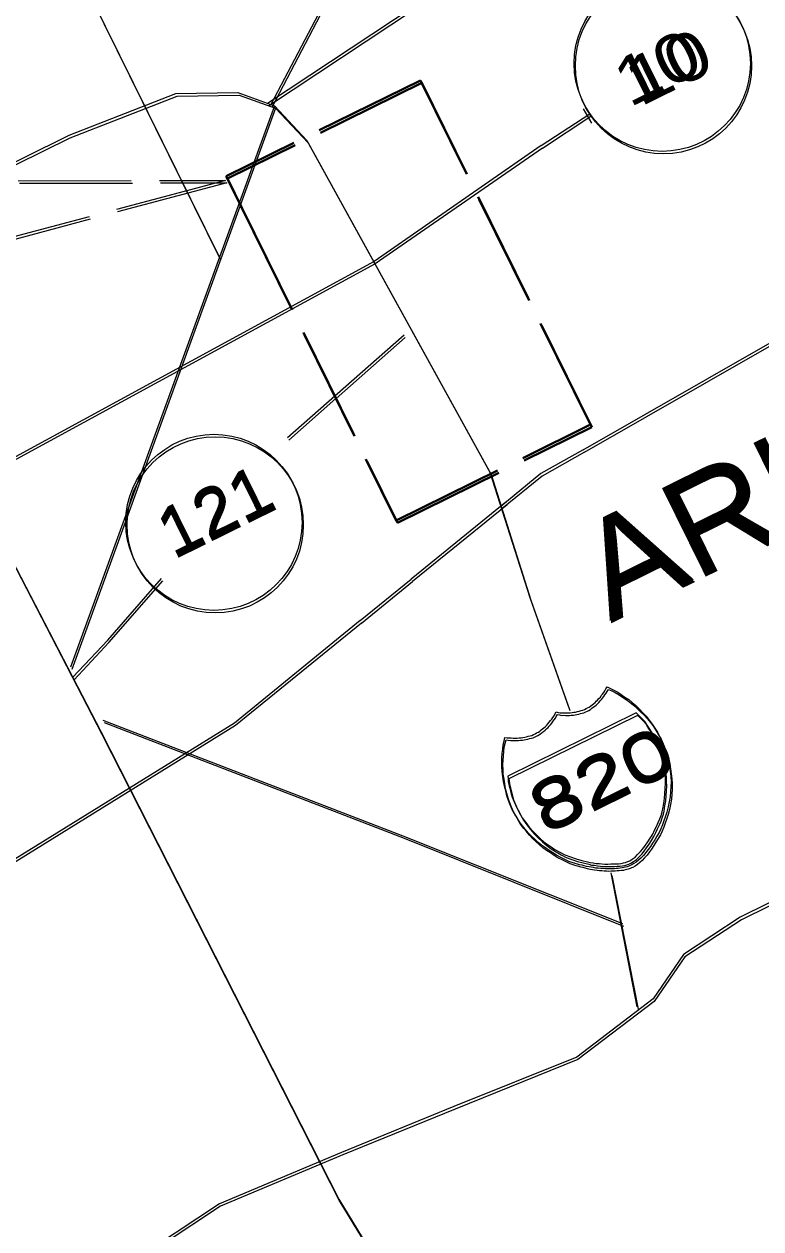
# Model space of a CAD drawing. Extents: x 2356606 to 2371222, y 6973096 to 6982644.
# Drawn here: x 2357285.3 to 2357363.6, y 6973619.6 to 6973747.7 of the extents above; entities that cross this region are included whole.
import ezdxf

# ---------------------------------------------------------------- set-up
doc = ezdxf.new("R2010")
doc.units = 0
doc.header["$LTSCALE"] = 2
doc.linetypes.add('LONG_DASHED', pattern=[7.5, 6, -1.5])
doc.layers.add('62', color=7, linetype='Continuous', lineweight=13)
doc.layers.add('63', color=7, linetype='Continuous', lineweight=13)

msp = doc.modelspace()

# ---------------------------------------------------------------- linework, layer by layer
at = {"layer": '62'}
for p, q in [((2357306.189, 6973722.639), (2357286.779, 6973761.966)), ((2357312.029, 6973738.72), (2357290.372, 6973679.028)), ((2357340.392, 6973734.479), (2357345.545, 6973737.873)), ((2357344.863, 6973738.391), (2357345.59, 6973737.12)), ((2357318.452, 6973707.86), (2357325.81, 6973714.355)), ((2357313.435, 6973703.432), (2357318.451, 6973707.861)), ((2357294.325, 6973681.906), (2357300.042, 6973688.465)), ((2357294.325, 6973681.906), (2357290.63, 6973677.95))]:
    msp.add_line(p, q, dxfattribs=at)
at = {"layer": '62', "lineweight": 25}
for p, q in [((2357312.029, 6973738.72), (2357315.48, 6973735.03)), ((2357315.48, 6973735.03), (2357334.942, 6973699.767)), ((2357344.853, 6973702.151), (2357364.72, 6973713.512)), ((2357336.626, 6973696.558), (2357326.581, 6973688.388)), ((2357321.156, 6973683.979), (2357326.581, 6973688.388)), ((2357347.774, 6973657.142), (2357350.558, 6973642.91))]:
    msp.add_line(p, q, dxfattribs=at)
at = {"layer": '62'}
for points in [[(2357324.805, 6973765.304), (2357320.284, 6973755.34), (2357311.656, 6973738.864)], [(2357311.295, 6973738.987), (2357326.895, 6973749.32), (2357341.679, 6973758.824)], [(2357340.392, 6973734.479), (2357322.629, 6973722.171), (2357280.124, 6973699.034), (2357274.052, 6973694.657)], [(2357342.838, 6973674.156), (2357343.061, 6973674.166), (2357343.263, 6973674.163), (2357343.454, 6973674.183), (2357343.675, 6973674.192), (2357343.856, 6973674.231), (2357344.048, 6973674.249), (2357344.25, 6973674.3), (2357344.42, 6973674.359), (2357344.621, 6973674.408), (2357344.802, 6973674.447), (2357344.985, 6973674.538), (2357345.166, 6973674.627), (2357345.308, 6973674.697), (2357345.489, 6973674.786), (2357345.65, 6973674.916), (2357345.792, 6973675.036), (2357345.946, 6973675.135), (2357346.104, 6973675.266), (2357346.238, 6973675.407), (2357346.377, 6973675.526), (2357346.52, 6973675.697), (2357346.671, 6973675.847), (2357346.773, 6973675.998), (2357346.915, 6973676.168), (2357347.026, 6973676.348), (2357347.147, 6973676.51), (2357347.268, 6973676.717), (2357347.391, 6973676.929), (2357347.754, 6973676.758), (2357348.115, 6973676.582), (2357348.526, 6973676.359), (2357348.896, 6973676.117), (2357349.279, 6973675.852), (2357349.69, 6973675.579), (2357350.07, 6973675.264), (2357350.431, 6973674.941), (2357350.82, 6973674.558), (2357351.182, 6973674.183), (2357351.541, 6973673.808), (2357351.872, 6973673.395), (2357352.181, 6973672.971), (2357352.47, 6973672.535), (2357352.731, 6973672.111), (2357352.991, 6973671.637), (2357353.208, 6973671.144), (2357353.426, 6973670.598), (2357353.616, 6973670.064), (2357353.785, 6973669.572), (2357353.923, 6973669.036), (2357354, 6973668.473), (2357354.079, 6973667.961), (2357354.145, 6973667.414), (2357354.183, 6973666.883), (2357354.161, 6973666.317), (2357354.137, 6973665.804), (2357354.086, 6973665.249), (2357353.981, 6973664.697), (2357353.887, 6973664.173), (2357353.733, 6973663.622), (2357353.573, 6973663.089), (2357353.416, 6973662.687), (2357353.274, 6973662.265), (2357353.101, 6973661.854), (2357352.917, 6973661.462), (2357352.682, 6973661.069), (2357352.45, 6973660.681), (2357352.228, 6973660.319), (2357351.984, 6973659.949), (2357351.761, 6973659.638), (2357351.518, 6973659.317), (2357351.245, 6973659.006), (2357350.982, 6973658.726), (2357350.748, 6973658.537), (2357350.487, 6973658.305), (2357350.245, 6973658.136), (2357350.011, 6973657.996)], [(2357350.011, 6973657.996), (2357349.841, 6973657.937), (2357349.7, 6973657.867), (2357349.507, 6973657.797), (2357349.348, 6973657.767), (2357349.166, 6973657.729), (2357348.985, 6973657.688), (2357348.773, 6973657.661), (2357348.559, 6973657.63), (2357348.342, 6973657.622), (2357348.129, 6973657.593), (2357347.876, 6973657.594), (2357347.677, 6973657.595), (2357347.434, 6973657.577), (2357347.202, 6973657.586), (2357346.941, 6973657.609), (2357346.71, 6973657.621), (2357346.447, 6973657.642), (2357346.187, 6973657.664), (2357345.937, 6973657.715), (2357345.713, 6973657.757), (2357345.472, 6973657.788), (2357345.192, 6973657.85), (2357344.939, 6973657.901), (2357344.729, 6973657.974), (2357344.457, 6973658.015), (2357344.246, 6973658.086), (2357343.985, 6973658.158), (2357343.774, 6973658.228), (2357343.532, 6973658.311), (2357343.323, 6973658.382), (2357343.121, 6973658.485), (2357342.899, 6973658.576), (2357342.468, 6973658.787), (2357342.026, 6973659.023), (2357341.623, 6973659.278), (2357341.244, 6973659.541), (2357340.833, 6973659.813), (2357340.42, 6973660.089), (2357340.069, 6973660.393), (2357339.701, 6973660.738), (2357339.35, 6973661.042), (2357339.01, 6973661.427), (2357338.699, 6973661.8), (2357338.39, 6973662.174), (2357338.088, 6973662.578), (2357337.83, 6973663.001), (2357337.551, 6973663.466), (2357337.31, 6973663.9), (2357337.092, 6973664.393), (2357336.913, 6973664.858), (2357336.746, 6973665.351), (2357336.616, 6973665.866), (2357336.47, 6973666.37), (2357336.392, 6973666.882), (2357336.312, 6973667.396), (2357336.226, 6973667.931), (2357336.209, 6973668.423), (2357336.19, 6973668.917), (2357336.201, 6973669.397), (2357336.245, 6973669.873), (2357336.298, 6973670.326), (2357336.33, 6973670.768), (2357336.434, 6973671.17), (2357336.517, 6973671.563), (2357336.758, 6973671.531), (2357336.999, 6973671.499), (2357337.201, 6973671.497), (2357337.411, 6973671.479), (2357337.632, 6973671.486), (2357337.833, 6973671.485), (2357338.046, 6973671.515), (2357338.267, 6973671.523), (2357338.429, 6973671.553), (2357338.64, 6973671.582), (2357338.821, 6973671.621), (2357339.01, 6973671.689), (2357339.213, 6973671.739), (2357339.396, 6973671.777), (2357339.556, 6973671.858), (2357339.74, 6973671.947), (2357339.9, 6973672.028), (2357340.082, 6973672.118), (2357340.225, 6973672.239), (2357340.385, 6973672.366), (2357340.516, 6973672.457), (2357340.678, 6973672.586), (2357340.829, 6973672.736), (2357340.992, 6973672.868), (2357341.092, 6973673.018), (2357341.244, 6973673.17), (2357341.386, 6973673.339), (2357341.507, 6973673.499), (2357341.622, 6973673.679), (2357341.76, 6973673.85), (2357341.845, 6973674.04), (2357341.984, 6973674.261), (2357342.185, 6973674.21), (2357342.406, 6973674.168), (2357342.627, 6973674.177), (2357342.838, 6973674.156)], [(2357349.044, 6973651.722), (2357325.734, 6973661.072), (2357293.846, 6973673.362)]]:
    msp.add_lwpolyline(points, dxfattribs=at)
at = {"layer": '62', "linetype": 'LONG_DASHED', "lineweight": 40}
msp.add_lwpolyline([(2357308.481, 6973728.063), (2357324.982, 6973694.628), (2357345.626, 6973704.814), (2357327.561, 6973741.417), (2357306.917, 6973731.231)], close=True, dxfattribs=at)
at = {"layer": '62', "lineweight": 25}
for points in [[(2357222.847, 6973670.893), (2357228.918, 6973681.166), (2357239.427, 6973691.649), (2357246.285, 6973700.327), (2357253.234, 6973708.874), (2357262, 6973718.52), (2357266.949, 6973724.101), (2357275.91, 6973728.522), (2357290.215, 6973735.582), (2357301.579, 6973740.013), (2357308.151, 6973740.118), (2357312.029, 6973738.72)], [(2357271.1, 6973715.534), (2357293.579, 6973672.174), (2357318.873, 6973622.455), (2357356.041, 6973561.379), (2357384.703, 6973540.469)], [(2357344.853, 6973702.151), (2357340.364, 6973699.609), (2357336.089, 6973696.118)], [(2357334.942, 6973699.767), (2357339.169, 6973686.421), (2357343.306, 6973674.686)], [(2357321.156, 6973683.979), (2357307.783, 6973673.088), (2357282.978, 6973657.708), (2357265.622, 6973642.845), (2357259.668, 6973639.454)], [(2357397.532, 6973674.071), (2357391.187, 6973669.235), (2357382.618, 6973664.025), (2357370.494, 6973656.862), (2357361.535, 6973652.442), (2357355.506, 6973648.488), (2357352.272, 6973643.756), (2357344.159, 6973637.568), (2357331.099, 6973632.303), (2357319.179, 6973627.424), (2357306.189, 6973621.966), (2357287.579, 6973609.643), (2357267.547, 6973602.895), (2357250.669, 6973598.906), (2357239.274, 6973599.379), (2357230.661, 6973609.861), (2357224.807, 6973621.723), (2357220.224, 6973626.738), (2357220.552, 6973637.313)]]:
    msp.add_lwpolyline(points, dxfattribs=at)
at = {"layer": '62', "linetype": 'LONG_DASHED'}
for points in [[(2357239.812, 6973730.633), (2357306.835, 6973730.788), (2357247.289, 6973714.873)], [(2357239.812, 6973730.633), (2357306.835, 6973730.788), (2357247.289, 6973714.873), (2357239.812, 6973730.633)]]:
    msp.add_lwpolyline(points, close=True, dxfattribs=at)
at = {"layer": '62'}
msp.add_lwpolyline([(2357350.487, 6973674.166), (2357336.827, 6973667.424), (2357336.863, 6973667.193), (2357336.892, 6973666.88), (2357336.953, 6973666.559), (2357337.071, 6973666.165), (2357337.17, 6973665.712), (2357337.297, 6973665.197), (2357337.515, 6973664.704), (2357337.775, 6973664.13), (2357338.064, 6973663.592), (2357338.372, 6973663.019), (2357338.743, 6973662.525), (2357339.112, 6973662.029), (2357339.523, 6973661.555), (2357339.924, 6973661.149), (2357340.393, 6973660.705), (2357340.856, 6973660.331), (2357341.329, 6973659.983), (2357341.837, 6973659.658), (2357342.374, 6973659.343), (2357342.915, 6973659.06), (2357343.496, 6973658.845), (2357344.098, 6973658.642), (2357344.7, 6973658.486), (2357345.324, 6973658.341), (2357345.595, 6973658.249), (2357345.908, 6973658.229), (2357346.24, 6973658.166), (2357346.551, 6973658.145), (2357346.842, 6973658.111), (2357347.154, 6973658.091), (2357347.455, 6973658.089), (2357347.779, 6973658.099), (2357348.051, 6973658.108), (2357348.321, 6973658.115), (2357348.614, 6973658.133), (2357348.876, 6973658.163), (2357349.128, 6973658.211), (2357349.349, 6973658.271), (2357349.579, 6973658.36), (2357349.794, 6973658.44), (2357350.056, 6973658.618), (2357350.378, 6973658.829), (2357350.621, 6973659.1), (2357350.945, 6973659.41), (2357351.199, 6973659.71), (2357351.462, 6973660.09), (2357351.726, 6973660.472), (2357351.968, 6973660.844), (2357352.234, 6973661.274), (2357352.426, 6973661.697), (2357352.63, 6973662.098), (2357352.824, 6973662.519), (2357353.005, 6973662.909), (2357353.128, 6973663.271), (2357353.24, 6973663.654), (2357353.314, 6973663.965), (2357353.406, 6973664.539), (2357353.489, 6973665.083), (2357353.532, 6973665.606), (2357353.566, 6973666.149), (2357353.598, 6973666.644), (2357353.58, 6973667.137), (2357353.571, 6973667.61), (2357353.514, 6973668.084), (2357353.456, 6973668.557), (2357353.378, 6973668.969), (2357353.28, 6973669.421), (2357353.132, 6973669.825), (2357353.001, 6973670.239), (2357352.854, 6973670.642), (2357352.684, 6973671.034), (2357352.525, 6973671.407), (2357352.225, 6973671.964), (2357351.947, 6973672.429), (2357351.638, 6973672.853), (2357351.397, 6973673.236), (2357351.119, 6973673.551), (2357350.878, 6973673.782), (2357350.668, 6973674.004)], close=True, dxfattribs=at)
for centre in [(2357353.248, 6973743.227), (2357305.613, 6973694.422)]:
    msp.add_circle(centre, 9.364, dxfattribs=at)
at = {"layer": '63'}
for p, q in [((2357306.059, 6973722.902), (2357286.649, 6973762.229)), ((2357311.899, 6973738.983), (2357290.242, 6973679.291)), ((2357340.262, 6973734.742), (2357345.415, 6973738.136)), ((2357344.733, 6973738.654), (2357345.46, 6973737.383)), ((2357318.321, 6973708.124), (2357325.679, 6973714.619)), ((2357313.305, 6973703.695), (2357318.321, 6973708.124)), ((2357294.195, 6973682.169), (2357299.912, 6973688.728)), ((2357294.195, 6973682.169), (2357290.5, 6973678.213))]:
    msp.add_line(p, q, dxfattribs=at)
at = {"layer": '63', "lineweight": 25}
for p, q in [((2357311.899, 6973738.983), (2357315.35, 6973735.293)), ((2357315.349, 6973735.294), (2357334.811, 6973700.031)), ((2357344.723, 6973702.414), (2357364.59, 6973713.775)), ((2357336.496, 6973696.821), (2357326.451, 6973688.651)), ((2357321.026, 6973684.242), (2357326.451, 6973688.651)), ((2357347.644, 6973657.405), (2357350.428, 6973643.173))]:
    msp.add_line(p, q, dxfattribs=at)
at = {"layer": '63'}
for points in [[(2357324.675, 6973765.567), (2357320.154, 6973755.603), (2357311.526, 6973739.127)], [(2357311.165, 6973739.25), (2357326.765, 6973749.583), (2357341.549, 6973759.087)], [(2357340.262, 6973734.742), (2357322.499, 6973722.434), (2357279.994, 6973699.297), (2357273.922, 6973694.92)], [(2357342.708, 6973674.419), (2357342.931, 6973674.429), (2357343.133, 6973674.426), (2357343.324, 6973674.446), (2357343.545, 6973674.455), (2357343.726, 6973674.494), (2357343.918, 6973674.512), (2357344.12, 6973674.563), (2357344.29, 6973674.622), (2357344.491, 6973674.671), (2357344.672, 6973674.71), (2357344.855, 6973674.801), (2357345.036, 6973674.89), (2357345.178, 6973674.96), (2357345.359, 6973675.049), (2357345.52, 6973675.179), (2357345.662, 6973675.299), (2357345.816, 6973675.398), (2357345.974, 6973675.529), (2357346.108, 6973675.67), (2357346.247, 6973675.789), (2357346.39, 6973675.96), (2357346.541, 6973676.11), (2357346.643, 6973676.261), (2357346.785, 6973676.431), (2357346.896, 6973676.611), (2357347.017, 6973676.773), (2357347.138, 6973676.98), (2357347.261, 6973677.192), (2357347.624, 6973677.021), (2357347.985, 6973676.845), (2357348.396, 6973676.622), (2357348.766, 6973676.38), (2357349.149, 6973676.115), (2357349.56, 6973675.842), (2357349.94, 6973675.527), (2357350.301, 6973675.204), (2357350.69, 6973674.821), (2357351.052, 6973674.446), (2357351.411, 6973674.071), (2357351.742, 6973673.658), (2357352.051, 6973673.234), (2357352.34, 6973672.798), (2357352.601, 6973672.374), (2357352.861, 6973671.9), (2357353.078, 6973671.407), (2357353.296, 6973670.861), (2357353.486, 6973670.327), (2357353.655, 6973669.835), (2357353.793, 6973669.299), (2357353.87, 6973668.736), (2357353.949, 6973668.224), (2357354.015, 6973667.677), (2357354.053, 6973667.146), (2357354.031, 6973666.58), (2357354.007, 6973666.067), (2357353.956, 6973665.512), (2357353.851, 6973664.96), (2357353.757, 6973664.436), (2357353.603, 6973663.885), (2357353.443, 6973663.352), (2357353.286, 6973662.95), (2357353.144, 6973662.528), (2357352.971, 6973662.117), (2357352.787, 6973661.725), (2357352.552, 6973661.332), (2357352.32, 6973660.944), (2357352.098, 6973660.582), (2357351.854, 6973660.212), (2357351.631, 6973659.901), (2357351.388, 6973659.58), (2357351.115, 6973659.269), (2357350.852, 6973658.989), (2357350.618, 6973658.8), (2357350.357, 6973658.568), (2357350.115, 6973658.399), (2357349.881, 6973658.259)], [(2357349.881, 6973658.259), (2357349.711, 6973658.2), (2357349.57, 6973658.13), (2357349.377, 6973658.06), (2357349.218, 6973658.03), (2357349.036, 6973657.992), (2357348.855, 6973657.951), (2357348.643, 6973657.924), (2357348.429, 6973657.893), (2357348.212, 6973657.885), (2357347.999, 6973657.856), (2357347.746, 6973657.857), (2357347.547, 6973657.858), (2357347.304, 6973657.84), (2357347.072, 6973657.849), (2357346.811, 6973657.872), (2357346.58, 6973657.884), (2357346.317, 6973657.905), (2357346.057, 6973657.927), (2357345.807, 6973657.978), (2357345.583, 6973658.02), (2357345.342, 6973658.051), (2357345.062, 6973658.113), (2357344.809, 6973658.164), (2357344.599, 6973658.237), (2357344.327, 6973658.278), (2357344.116, 6973658.349), (2357343.855, 6973658.421), (2357343.644, 6973658.491), (2357343.402, 6973658.574), (2357343.193, 6973658.645), (2357342.991, 6973658.748), (2357342.769, 6973658.839), (2357342.338, 6973659.05), (2357341.896, 6973659.286), (2357341.493, 6973659.541), (2357341.114, 6973659.804), (2357340.703, 6973660.076), (2357340.29, 6973660.352), (2357339.939, 6973660.656), (2357339.571, 6973661.001), (2357339.22, 6973661.305), (2357338.88, 6973661.69), (2357338.569, 6973662.063), (2357338.26, 6973662.437), (2357337.958, 6973662.841), (2357337.7, 6973663.264), (2357337.421, 6973663.729), (2357337.18, 6973664.163), (2357336.962, 6973664.656), (2357336.783, 6973665.121), (2357336.616, 6973665.614), (2357336.486, 6973666.129), (2357336.34, 6973666.633), (2357336.262, 6973667.145), (2357336.182, 6973667.659), (2357336.096, 6973668.194), (2357336.079, 6973668.686), (2357336.06, 6973669.18), (2357336.071, 6973669.66), (2357336.115, 6973670.136), (2357336.168, 6973670.589), (2357336.2, 6973671.031), (2357336.304, 6973671.433), (2357336.387, 6973671.826), (2357336.628, 6973671.794), (2357336.869, 6973671.762), (2357337.071, 6973671.76), (2357337.281, 6973671.742), (2357337.502, 6973671.749), (2357337.703, 6973671.748), (2357337.916, 6973671.778), (2357338.137, 6973671.786), (2357338.299, 6973671.816), (2357338.51, 6973671.845), (2357338.691, 6973671.884), (2357338.88, 6973671.952), (2357339.083, 6973672.002), (2357339.266, 6973672.04), (2357339.426, 6973672.121), (2357339.61, 6973672.21), (2357339.77, 6973672.291), (2357339.952, 6973672.381), (2357340.095, 6973672.502), (2357340.255, 6973672.629), (2357340.386, 6973672.72), (2357340.548, 6973672.849), (2357340.699, 6973672.999), (2357340.862, 6973673.131), (2357340.962, 6973673.281), (2357341.114, 6973673.433), (2357341.256, 6973673.602), (2357341.377, 6973673.762), (2357341.492, 6973673.942), (2357341.63, 6973674.113), (2357341.715, 6973674.303), (2357341.854, 6973674.524), (2357342.055, 6973674.473), (2357342.276, 6973674.431), (2357342.497, 6973674.44), (2357342.708, 6973674.419)], [(2357348.914, 6973651.985), (2357325.604, 6973661.335), (2357293.716, 6973673.625)]]:
    msp.add_lwpolyline(points, dxfattribs=at)
at = {"layer": '63', "linetype": 'LONG_DASHED', "lineweight": 40}
msp.add_lwpolyline([(2357308.351, 6973728.326), (2357324.852, 6973694.891), (2357345.496, 6973705.077), (2357327.431, 6973741.68), (2357306.787, 6973731.494)], close=True, dxfattribs=at)
at = {"layer": '63', "lineweight": 25}
for points in [[(2357222.717, 6973671.156), (2357228.788, 6973681.429), (2357239.297, 6973691.912), (2357246.155, 6973700.59), (2357253.104, 6973709.137), (2357261.87, 6973718.783), (2357266.819, 6973724.364), (2357275.78, 6973728.785), (2357290.085, 6973735.845), (2357301.449, 6973740.276), (2357308.021, 6973740.381), (2357311.899, 6973738.983)], [(2357270.97, 6973715.797), (2357293.449, 6973672.437), (2357318.743, 6973622.718), (2357355.911, 6973561.642), (2357384.573, 6973540.732)], [(2357344.723, 6973702.414), (2357340.234, 6973699.872), (2357335.959, 6973696.381)], [(2357334.812, 6973700.03), (2357339.039, 6973686.684), (2357343.176, 6973674.949)], [(2357321.026, 6973684.242), (2357307.653, 6973673.351), (2357282.848, 6973657.971), (2357265.492, 6973643.108), (2357259.538, 6973639.717)], [(2357397.402, 6973674.334), (2357391.057, 6973669.498), (2357382.488, 6973664.288), (2357370.364, 6973657.125), (2357361.405, 6973652.705), (2357355.376, 6973648.751), (2357352.142, 6973644.019), (2357344.029, 6973637.831), (2357330.969, 6973632.566), (2357319.049, 6973627.687), (2357306.059, 6973622.229), (2357287.449, 6973609.906), (2357267.417, 6973603.158), (2357250.539, 6973599.169), (2357239.144, 6973599.642), (2357230.531, 6973610.124), (2357224.677, 6973621.986), (2357220.094, 6973627.001), (2357220.422, 6973637.576)]]:
    msp.add_lwpolyline(points, dxfattribs=at)
at = {"layer": '63', "linetype": 'LONG_DASHED'}
for points in [[(2357239.682, 6973730.896), (2357306.705, 6973731.051), (2357247.159, 6973715.136)], [(2357239.682, 6973730.896), (2357306.705, 6973731.051), (2357247.159, 6973715.136), (2357239.682, 6973730.896)]]:
    msp.add_lwpolyline(points, close=True, dxfattribs=at)
at = {"layer": '63'}
msp.add_lwpolyline([(2357350.357, 6973674.429), (2357336.697, 6973667.687), (2357336.733, 6973667.456), (2357336.762, 6973667.143), (2357336.823, 6973666.822), (2357336.941, 6973666.428), (2357337.04, 6973665.975), (2357337.167, 6973665.46), (2357337.385, 6973664.967), (2357337.645, 6973664.393), (2357337.934, 6973663.855), (2357338.242, 6973663.282), (2357338.613, 6973662.788), (2357338.982, 6973662.292), (2357339.393, 6973661.818), (2357339.794, 6973661.412), (2357340.263, 6973660.968), (2357340.726, 6973660.594), (2357341.199, 6973660.246), (2357341.707, 6973659.921), (2357342.244, 6973659.606), (2357342.785, 6973659.323), (2357343.366, 6973659.108), (2357343.968, 6973658.905), (2357344.57, 6973658.749), (2357345.194, 6973658.604), (2357345.465, 6973658.512), (2357345.778, 6973658.492), (2357346.11, 6973658.429), (2357346.421, 6973658.408), (2357346.712, 6973658.374), (2357347.024, 6973658.354), (2357347.325, 6973658.352), (2357347.649, 6973658.362), (2357347.921, 6973658.371), (2357348.191, 6973658.378), (2357348.484, 6973658.396), (2357348.746, 6973658.426), (2357348.998, 6973658.474), (2357349.219, 6973658.534), (2357349.449, 6973658.623), (2357349.664, 6973658.703), (2357349.926, 6973658.881), (2357350.248, 6973659.092), (2357350.491, 6973659.363), (2357350.815, 6973659.673), (2357351.069, 6973659.973), (2357351.332, 6973660.353), (2357351.596, 6973660.735), (2357351.838, 6973661.107), (2357352.104, 6973661.537), (2357352.296, 6973661.96), (2357352.5, 6973662.361), (2357352.694, 6973662.782), (2357352.875, 6973663.172), (2357352.998, 6973663.534), (2357353.11, 6973663.917), (2357353.184, 6973664.228), (2357353.276, 6973664.802), (2357353.359, 6973665.346), (2357353.402, 6973665.869), (2357353.436, 6973666.412), (2357353.468, 6973666.907), (2357353.45, 6973667.4), (2357353.441, 6973667.873), (2357353.384, 6973668.347), (2357353.326, 6973668.82), (2357353.248, 6973669.232), (2357353.15, 6973669.684), (2357353.002, 6973670.088), (2357352.871, 6973670.502), (2357352.724, 6973670.905), (2357352.554, 6973671.297), (2357352.395, 6973671.67), (2357352.095, 6973672.227), (2357351.817, 6973672.692), (2357351.508, 6973673.116), (2357351.267, 6973673.499), (2357350.989, 6973673.814), (2357350.748, 6973674.045), (2357350.538, 6973674.267)], close=True, dxfattribs=at)
for centre in [(2357353.118, 6973743.49), (2357305.483, 6973694.686)]:
    msp.add_circle(centre, 9.364, dxfattribs=at)

# ---------------------------------------------------------------- texts
at = {"layer": '62'}
for s, height, width, p in [('10', 5.099, 1.2, (2357350.801, 6973738.85)), ('ARLINGTON', 10.21, 1.1, (2357347.651, 6973683.932)), ('121', 5.099, 1.1, (2357301.213, 6973690.676)), ('820', 5.099, 1.4, (2357340.73, 6973661.396))]:
    msp.add_text(s, height=height, rotation=26.268, dxfattribs=dict(at, width=width)).set_placement(p)
at = {"layer": '63'}
for s, height, width, p in [('10', 5.099, 1.2, (2357349.624, 6973738.76)), ('ARLINGTON', 10.21, 1.1, (2357347.521, 6973684.196)), ('121', 5.099, 1.1, (2357301.083, 6973690.94)), ('820', 5.099, 1.4, (2357340.6, 6973661.66))]:
    msp.add_text(s, height=height, rotation=26.268, dxfattribs=dict(at, width=width)).set_placement(p)

doc.saveas('drawing.dxf')
